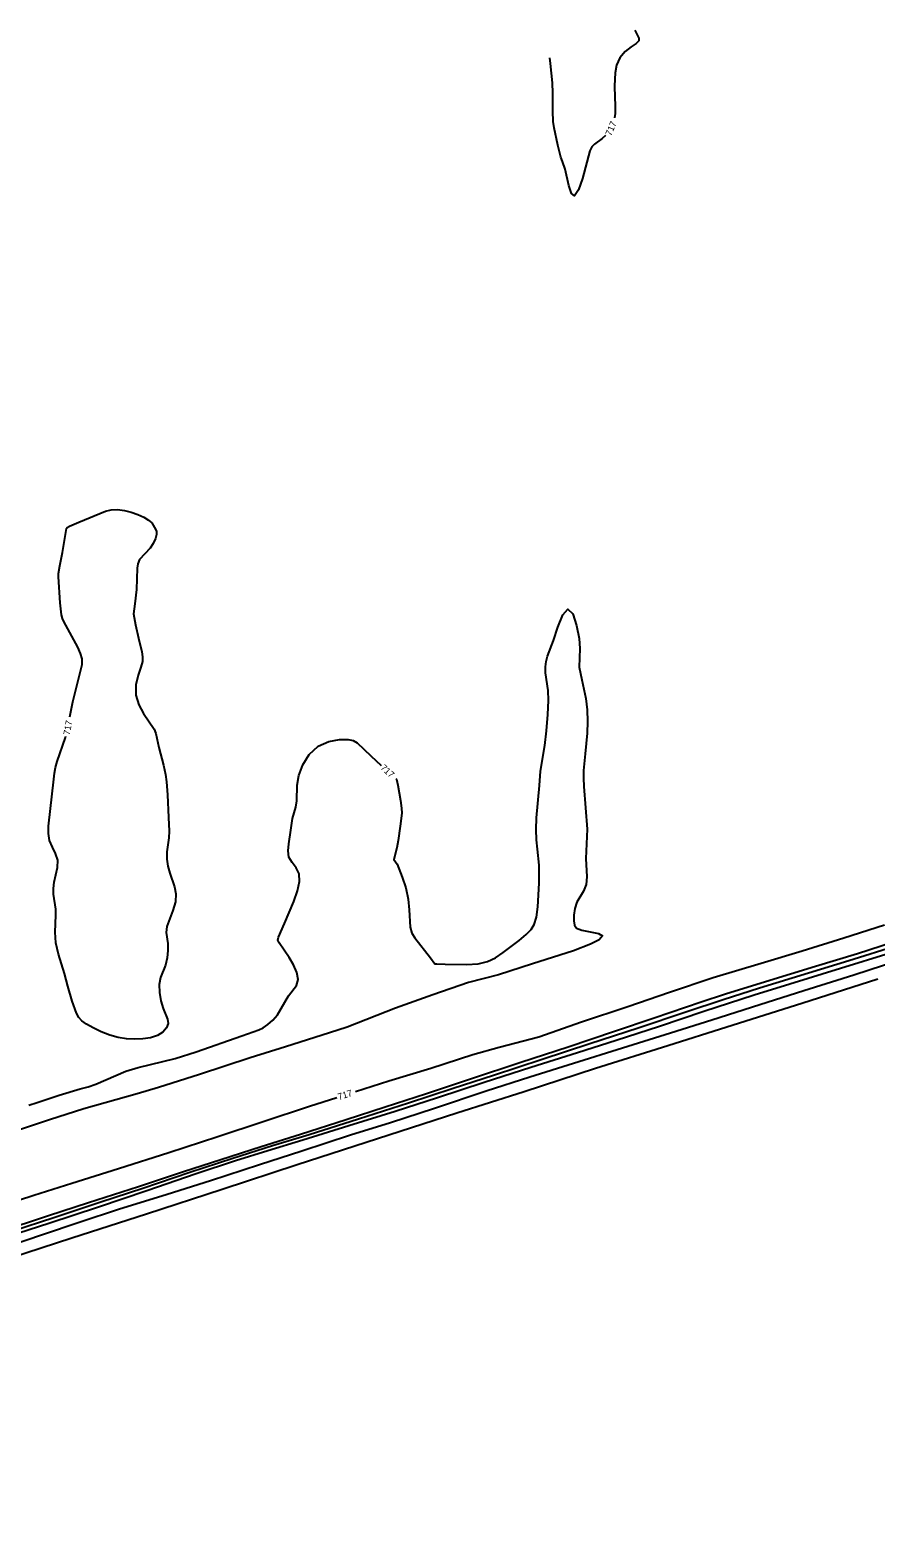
# Model space of a CAD drawing. Extents: x -361782338 to 28259792, y -263199453 to 8342113.
# Drawn here: x 1405176 to 1405692, y 576685 to 577607 of the extents above; entities that cross this region are included whole.
import ezdxf

# ---------------------------------------------------------------- set-up
doc = ezdxf.new("R2010")
doc.units = 0
for name, color, linetype in [('DT_X_Contour_Minor', 7, 'Continuous'), ('Level 14', 7, 'Continuous'), ('Level 19', 7, 'Continuous')]:
    doc.layers.add(name, color=color, linetype=linetype)

msp = doc.modelspace()

# ---------------------------------------------------------------- linework, layer by layer
at = {"layer": 'DT_X_Contour_Minor'}
for points in [[(1405545.36, 577606.81), (1405547.81, 577601.92), (1405547.75, 577600.19), (1405546.08, 577598.74), (1405542.98, 577596.63), (1405539.3, 577593.69), (1405536.08, 577589.93), (1405534.11, 577585.45), (1405533.19, 577580.74), (1405532.78, 577572.74), (1405533.04, 577565.6), (1405533.31, 577561.02), (1405533.28, 577555.97), (1405532.84, 577553.22)], [(1405527.38, 577542.5), (1405525.38, 577540.57), (1405520.63, 577537.2), (1405518.93, 577535.48), (1405517.75, 577532.99), (1405513.29, 577516.2), (1405510.87, 577509.27), (1405508.5, 577505.59), (1405506.55, 577507.04), (1405504.99, 577511.92), (1405502.67, 577521.91), (1405501.15, 577526.55), (1405500.1, 577529.12), (1405498.24, 577536.5), (1405495.99, 577547.2), (1405495.42, 577550.88), (1405495.19, 577557.39), (1405495.16, 577568.26), (1405494.92, 577574.63), (1405493.76, 577586.41), (1405493.27, 577589.93)], [(1405200.19, 577187.11), (1405201.91, 577196.34), (1405207.78, 577219.16), (1405207.64, 577222.47), (1405206.71, 577225.82), (1405204.99, 577229.57), (1405196.49, 577245.39), (1405195.73, 577247.27), (1405195.15, 577249.38), (1405194.26, 577256.78), (1405193.14, 577272.68), (1405193.21, 577274.8), (1405194.06, 577279.3), (1405195.59, 577287.53), (1405198.02, 577302.2), (1405198.62, 577302.84), (1405199.87, 577303.57), (1405205.7, 577306.03), (1405221.88, 577312.74), (1405225.49, 577313.6), (1405229.37, 577313.72), (1405233.45, 577313.19), (1405237.62, 577312.15), (1405241.71, 577310.74), (1405245.38, 577309.1), (1405248.29, 577307.34), (1405250.17, 577305.59), (1405252.73, 577301.46), (1405253.18, 577300.27), (1405253.16, 577298.56), (1405252.47, 577296.05), (1405251.14, 577293.09), (1405249.24, 577290.18), (1405242.66, 577283.24), (1405241.6, 577280.69), (1405241.19, 577277.91), (1405240.84, 577264.99), (1405239.89, 577256.17), (1405239.09, 577250), (1405240.23, 577243.36), (1405242.14, 577235.14), (1405244.18, 577226.73), (1405244.62, 577223.7), (1405244.44, 577220.89), (1405243.52, 577217.39), (1405241.91, 577212.51), (1405240.5, 577206.65), (1405240.37, 577200.42), (1405242.21, 577194.43), (1405245.23, 577189.08), (1405251.57, 577179.51), (1405252.59, 577176.86), (1405254.47, 577168.42), (1405257.28, 577157.59), (1405258.54, 577151.94), (1405259.28, 577147.3), (1405259.76, 577139.35), (1405260.33, 577125.63), (1405260.8, 577117.29), (1405260.65, 577113.2), (1405259.47, 577104.55), (1405259.31, 577100.14), (1405259.93, 577095.8), (1405261.15, 577091.54), (1405264.05, 577083.16), (1405264.88, 577078.8), (1405264.65, 577074.05), (1405263.09, 577068.81), (1405259.37, 577058.88), (1405259, 577055.2), (1405259.99, 577048.55), (1405260.06, 577044.36), (1405259.54, 577039.77), (1405258.49, 577035.33), (1405255.57, 577027.69), (1405254.71, 577023.53), (1405254.84, 577018.62), (1405255.78, 577013.47), (1405257.19, 577008.82), (1405259.88, 577002.3), (1405260.16, 576999.69), (1405259.16, 576997), (1405256.92, 576994.44), (1405253.62, 576992.34), (1405249.42, 576990.97), (1405244.65, 576990.25), (1405239.65, 576990.06), (1405234.69, 576990.31), (1405229.72, 576991.06), (1405224.6, 576992.45), (1405219.33, 576994.52), (1405214.38, 576996.93), (1405210.3, 576999.27), (1405207.5, 577001.29), (1405205.65, 577003.34), (1405204.25, 577005.94), (1405201.57, 577013.32), (1405198.92, 577022.45), (1405196.92, 577030.23), (1405193.13, 577042.04), (1405191.64, 577049.03)], [(1405399.2, 577149.34), (1405399.63, 577148.95), (1405400.52, 577145.3), (1405402.23, 577135.94), (1405402.84, 577131.36), (1405402.96, 577128.26), (1405401.85, 577120.17), (1405400.69, 577111.42), (1405399.89, 577107.08), (1405398.01, 577099.89), (1405400.07, 577097.12), (1405403.22, 577089.12), (1405405.32, 577082.66), (1405406.91, 577075.72), (1405407.52, 577069.15), (1405407.95, 577058.56), (1405409.03, 577054.94), (1405410.84, 577052.01), (1405420.37, 577039.81), (1405423.18, 577036.14), (1405424.28, 577036.13), (1405429.48, 577036), (1405442.54, 577035.61), (1405449.55, 577036.1), (1405455.28, 577037.54), (1405460.11, 577039.86), (1405464.76, 577042.96), (1405474.65, 577050.47), (1405478.84, 577054), (1405481.86, 577057), (1405483.85, 577060.24), (1405485.15, 577064.71), (1405486.03, 577071.05), (1405486.91, 577085.48), (1405486.9, 577096.45), (1405485.84, 577106.29), (1405485.2, 577111.9), (1405484.94, 577118.23), (1405485.29, 577125.34), (1405487.03, 577145.05), (1405487.61, 577153.95), (1405490.36, 577169.62), (1405491.37, 577178.63), (1405492.15, 577188.46), (1405492.49, 577197.12), (1405492.29, 577203.14), (1405490.73, 577213.97), (1405490.66, 577217.57), (1405491.05, 577220.99), (1405492, 577224.16), (1405495.67, 577233.79), (1405498.33, 577241.84), (1405501.32, 577249.42), (1405504.39, 577252.97), (1405507.3, 577250.1), (1405509.68, 577243), (1405511.2, 577235), (1405511.65, 577228.76), (1405511.35, 577217.44), (1405512.91, 577209.75), (1405515.3, 577198.3), (1405516.13, 577191.45), (1405516.39, 577184.23), (1405516.17, 577177.07), (1405515.02, 577164.5), (1405514.01, 577154.37), (1405513.89, 577149.54), (1405514.08, 577144.45), (1405516.23, 577118.51), (1405515.35, 577100.52), (1405515.93, 577089.31), (1405515.52, 577084.53), (1405513.94, 577080.63), (1405509.74, 577073.77), (1405508.54, 577069.87), (1405508.07, 577065.88), (1405508.04, 577062.36), (1405508.39, 577059.71), (1405509.73, 577057.86), (1405512.86, 577056.6), (1405523.09, 577054.67), (1405525.49, 577053.15), (1405523.38, 577050.85), (1405518.28, 577048.18), (1405507.82, 577044.04), (1405482.66, 577036.05), (1405462.04, 577029.33), (1405443.68, 577024.75), (1405421.81, 577017.16), (1405399.07, 577009.1), (1405369.52, 576997.5), (1405358.82, 576993.92), (1405331.87, 576985.39), (1405310.3, 576978.66), (1405279.38, 576968.45), (1405254.38, 576960.56), (1405241.27, 576956.71), (1405208.71, 576947.55), (1405187.77, 576940.76), (1405156.39, 576930.36)], [(1405175.1, 576949.72), (1405180.3, 576951.44), (1405193.63, 576955.91), (1405206.47, 576959.66), (1405211.29, 576960.96), (1405216.04, 576962.6), (1405234.41, 576970.51), (1405241.92, 576972.73), (1405264.43, 576978.21), (1405277.28, 576982.26), (1405305.19, 576992.08), (1405315.54, 576995.72), (1405318.21, 576997.09), (1405321.18, 576999.05), (1405324.23, 577001.65), (1405327.03, 577004.9), (1405329.34, 577008.72), (1405331.44, 577012.74), (1405333.71, 577016.53), (1405338.64, 577022.92), (1405339.69, 577026.48), (1405338.89, 577030.84), (1405336.74, 577035.57), (1405334.05, 577040.05), (1405327.93, 577048.93), (1405327.3, 577050.56), (1405327.59, 577052.47), (1405331.25, 577060.81), (1405336.96, 577074.21), (1405339.22, 577080.7), (1405340.44, 577086.44), (1405340.22, 577091.18), (1405338.4, 577094.84), (1405335.93, 577097.97), (1405334, 577101.25), (1405333.51, 577105.17), (1405334.02, 577109.5), (1405335.23, 577117.78), (1405336.1, 577124.88), (1405338.19, 577131.79), (1405338.9, 577135.7), (1405339.03, 577145.34), (1405339.95, 577151.26), (1405342.41, 577157.82), (1405346.44, 577164.14), (1405351.89, 577169.15), (1405358.4, 577172.06), (1405364.91, 577173.22), (1405370.14, 577173.29), (1405373.32, 577172.72), (1405375.64, 577171.17), (1405383.92, 577163.33), (1405390.35, 577157.44)], [(1405191.64, 577049.03), (1405191.22, 577055.51), (1405191.7, 577065.9), (1405191.51, 577069.58), (1405190.08, 577078.62), (1405190.11, 577082.12), (1405190.65, 577086.06), (1405192.67, 577094.95), (1405192.76, 577099.38), (1405191.48, 577103.5), (1405189.52, 577107.45), (1405187.81, 577111.49), (1405187.09, 577115.79), (1405187.18, 577120.18), (1405190.32, 577149.02), (1405190.71, 577152.6), (1405191.35, 577156.05), (1405192.42, 577159.86), (1405197.56, 577174.47), (1405197.77, 577175.35)], [(1405156.77, 576872.21), (1405187.09, 576882.22), (1405211.58, 576890.24), (1405242.09, 576900.04), (1405269.5, 576909.17), (1405292.45, 576916.59), (1405316.95, 576924.49), (1405341.11, 576932), (1405368.98, 576940.99), (1405392.75, 576948.62), (1405417.93, 576956.95), (1405444.91, 576965.84), (1405475.68, 576975.96), (1405504.49, 576985.47), (1405532.92, 576994.92), (1405557.06, 577003.15), (1405585.75, 577012.93), (1405600.74, 577017.83), (1405625.11, 577025.32), (1405655.62, 577034.59), (1405681.24, 577042.5), (1405710.7, 577051.98)], [(1405374.68, 576958.12), (1405394.92, 576964.63), (1405420.59, 576972.27), (1405446.22, 576980.63), (1405462.5, 576985.19), (1405486.69, 576991.59), (1405512.75, 577000.58), (1405540.89, 577010), (1405566.5, 577018.71), (1405593.19, 577027.66), (1405622.38, 577036.52), (1405647.57, 577044.09), (1405673.02, 577051.93), (1405697.8, 577059.85)], [(1405705.99, 577047.41), (1405676.08, 577037.98), (1405651.4, 577030.38), (1405621.34, 577021.16), (1405599.29, 577014.21), (1405576.35, 577006.55), (1405547.38, 576996.81), (1405517.87, 576987.2), (1405488.58, 576977.64), (1405458.84, 576967.95), (1405434.25, 576959.95), (1405406.95, 576950.96), (1405376.45, 576941.19), (1405346.28, 576931.63), (1405324.04, 576924.84), (1405299.62, 576917.09), (1405273.38, 576908.58), (1405244.68, 576898.77), (1405219.1, 576890.41), (1405190.3, 576880.95), (1405165.34, 576872.73)], [(1405169.03, 576871.63), (1405187.23, 576877.63), (1405217.72, 576887.63), (1405247.27, 576897.49), (1405277.25, 576907.99), (1405301.29, 576915.82), (1405321.19, 576922.05), (1405342.46, 576928.46), (1405370.53, 576937.2), (1405398.84, 576945.96), (1405424.68, 576954.43), (1405453.2, 576963.72), (1405481.83, 576972.93), (1405510.17, 576981.97), (1405533.85, 576989.49), (1405560.31, 576998.09), (1405587.51, 577007.12), (1405618.07, 577017.13), (1405639.85, 577023.87), (1405670.92, 577033.45), (1405701.27, 577042.83)], [(1405678.95, 577029.34), (1405705.85, 577038.06)], [(1405154.52, 576860.91), (1405182.93, 576870.45), (1405206.52, 576878.44), (1405229.94, 576886.13), (1405259.56, 576895.27), (1405286.01, 576903.77), (1405315.94, 576913.44), (1405341.94, 576921.87), (1405371.51, 576931.52), (1405395.97, 576939.22), (1405422.91, 576947.91), (1405454.53, 576958.43), (1405481.18, 576967.01), (1405507.78, 576975.45), (1405537.72, 576984.68), (1405567.02, 576993.91), (1405592.25, 577001.94), (1405621.69, 577011.34), (1405648.47, 577019.75), (1405678.95, 577029.34)], [(1404940.58, 576818.62), (1404943.47, 576819.52), (1404973.37, 576828.68), (1404993.69, 576835.17), (1405018.38, 576843.3), (1405047.46, 576852.58), (1405070.35, 576860.14), (1405092.08, 576867.08), (1405122.36, 576876.53), (1405149.86, 576885.52), (1405178.1, 576894.8), (1405201.47, 576902.13), (1405229.94, 576911.05), (1405260.65, 576920.76), (1405290.61, 576930.48), (1405318.2, 576939.83), (1405346.47, 576949.16), (1405363.25, 576954.48)]]:
    msp.add_lwpolyline(points, dxfattribs=at)
at = {"layer": 'Level 14'}
msp.add_lwpolyline([(1405693.63, 577026.65), (1405647.23, 577011.88), (1405601.41, 576997.31), (1405565.47, 576986.03), (1405521.27, 576972.22), (1405477.58, 576957.8), (1405436.64, 576944.81), (1405394.97, 576931.31), (1405338.95, 576913.22), (1405293.27, 576898.15), (1405246.95, 576883.11), (1405201.35, 576868.47), (1405154.39, 576853.12), (1405105.93, 576837.31), (1405058.09, 576821.86), (1405009.55, 576806.2), (1404961.61, 576790.46), (1404915.2, 576775.33), (1404868.59, 576760), (1404822.97, 576745.16), (1404776.57, 576730.07), (1404728.75, 576714.56), (1404683.02, 576699.67), (1404638.14, 576685.26)], dxfattribs=at)

# ---------------------------------------------------------------- texts
at = {"layer": 'Level 19'}
for rotation, p in [(67.0246, (1405530.77, 577541.87)), (79.41195, (1405200.08, 577175.68)), (317.52175, (1405389.55, 577155.47)), (17.57834, (1405364.56, 576952.79))]:
    msp.add_text('717', height=4, rotation=rotation, dxfattribs=at).set_placement(p)

doc.saveas('drawing.dxf')
